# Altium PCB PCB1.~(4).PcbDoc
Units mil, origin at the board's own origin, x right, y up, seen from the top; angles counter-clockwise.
Board outline 6000 x 4000 mil, 2 copper layers (Top Layer, Bottom Layer); 2 components, 1 nets, 26 pads, 0 vias.
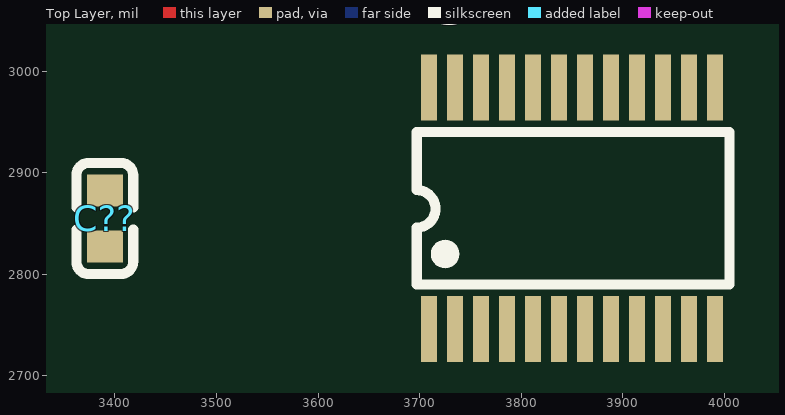
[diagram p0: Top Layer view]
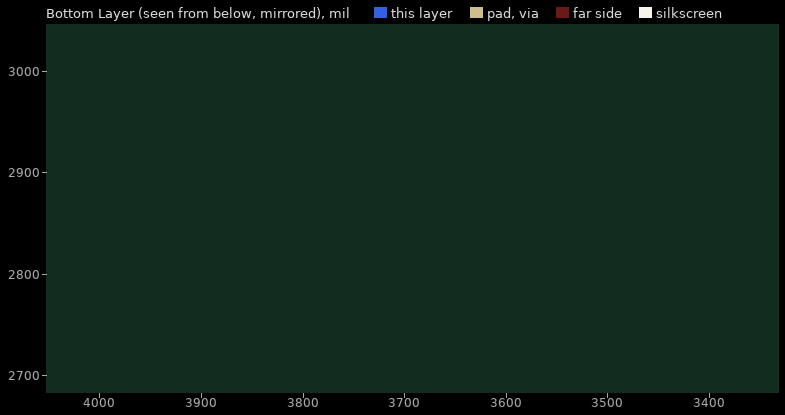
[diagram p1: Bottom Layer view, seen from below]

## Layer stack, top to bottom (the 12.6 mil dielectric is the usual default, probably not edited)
Top Solder: solder mask 0.4, Solder Resist, Dk 3.5
Top Layer: signal copper 1.4
Dielectric 1: dielectric 12.6, FR-4, Dk 4.8
Bottom Layer: signal copper 1.4
Bottom Solder: solder mask 0.4, Solder Resist, Dk 3.5

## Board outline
1000,1000 7000,1000 7000,5000 1000,5000

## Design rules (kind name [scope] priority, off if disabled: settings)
Clearance [All] p1: gap=10 ignorepadtopadclearanceinfootprint=FALSE
PolygonConnect [All] p1: connectstyle=Relief reliefconductorwidth=10 reliefentries=4 polygonreliefangle="90 Angle" airgapwidth=10
RoutingVias [All] p1: holewidth=28 width=50 viastyle="Through Hole" minholewidth=28 minwidth=50 maxholewidth=28 maxwidth=50
SolderMaskExpansion [All] p1: expansion=0 istentingtop=FALSE
SupplyNets "Schematic Supply Nets" [InNet('+5')] p1: voltage=0.000
Width [All] p1: maxlimit=10 minlimit=10 preferedwidth=10
30 further rules are at their usual default settings.

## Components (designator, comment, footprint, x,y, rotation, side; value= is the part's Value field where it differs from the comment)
C?? "cga0603x7r104k500jt" C0603 3390,2855 r90 top value=100nF
U?? "ads1232ipwr" TSSOP-24_L7.8-W4.4-P0.65-LS6.4-BL 3850,2865 r0 top

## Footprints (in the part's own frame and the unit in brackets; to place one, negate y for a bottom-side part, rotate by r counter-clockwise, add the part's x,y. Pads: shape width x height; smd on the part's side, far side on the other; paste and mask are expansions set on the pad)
C0603 [mm]
  rect 0.8x0.9 smd: 1(-0.7,0) 2(0.7,0)
  silkscreen extent -1.39,-0.71 1.39,0.71
TSSOP-24_L7.8-W4.4-P0.65-LS6.4-BL [mm]
  rect 0.4x1.65 smd: 1(-3.575,-3.023) 2(-2.925,-3.023) 3(-2.275,-3.023) 4(-1.625,-3.023) 5(-0.975,-3.023) 6(-0.325,-3.023) 7(0.325,-3.023) 8(0.975,-3.023) 9(1.625,-3.023) 10(2.275,-3.023) 11(2.925,-3.023) 12(3.575,-3.023) 13(3.575,3.023) 14(2.925,3.023) 15(2.275,3.023) 16(1.625,3.023) 17(0.975,3.023) 18(0.325,3.023) 19(-0.325,3.023) 20(-0.975,3.023) 21(-1.625,3.023) 22(-2.275,3.023) 23(-2.925,3.023) 24(-3.575,3.023)
  silkscreen extent -3.89,-1.91 3.94,1.91

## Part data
C??: "容值:100nF;精度:±10%;额定电压:50V;温度系数:X7R;", JLCPCB Part Class="Extended Part", LCSC Part Name="100nF ±10% 50V", Manufacturer=HRE(芯声), ManufacturerPart=CGA0603X7R104K500JT, Temperature Coefficient=X7R, Tolerance=±10%, Voltage Rating=50V
U??: "分辨率(位):24;采样率:10Hz;工作电压:2.7V~5.3V;接口类型:SPI;", Clock Frequency=4.9152MHz；200kHz~8MHz, JLCPCB Part Class="Extended Part", LCSC Part Name="用于桥式传感器的24bit 模数转换器", Manufacturer=TI(德州仪器), ManufacturerPart=ADS1232IPWR, Operating Temperature=-40℃~+105℃, Quiescent Current (Iq)=1.3uA, Temperature Sensors=内置, Voltage - Supply=2.7V~5.3V, Voltage Reference=外置, Voltage Reference Drift=-

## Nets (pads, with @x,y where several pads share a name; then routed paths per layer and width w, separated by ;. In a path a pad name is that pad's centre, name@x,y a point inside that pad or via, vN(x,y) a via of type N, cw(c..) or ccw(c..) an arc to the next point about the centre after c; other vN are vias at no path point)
+5: U??.1
pads on no net: C??.1 C??.2 U??.2 U??.3 U??.4 U??.5 U??.6 U??.7 U??.8 U??.9 U??.10 U??.11 U??.12 U??.13 U??.14 U??.15 U??.16 U??.17 U??.18 U??.19 U??.20 U??.21 U??.22 U??.23 U??.24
